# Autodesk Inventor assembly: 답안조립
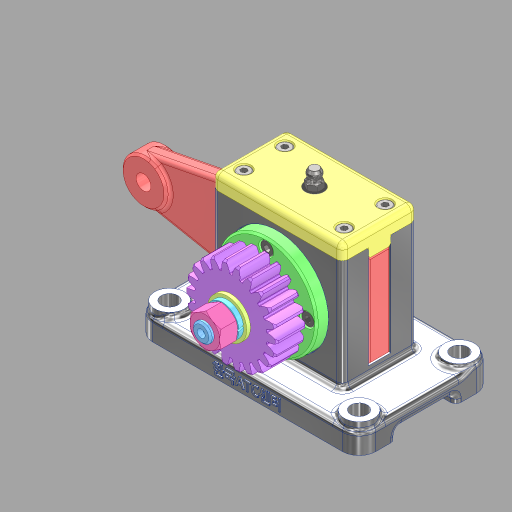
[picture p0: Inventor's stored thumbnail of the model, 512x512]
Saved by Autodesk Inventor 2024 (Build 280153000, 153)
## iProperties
Created: 2025-04
Part Number: 답안조립
Document SubType Name: Assembly
Designer: kh_501
Author: kh_501
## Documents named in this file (15)
- C:\Users\kh_501\Desktop\750404V1011\답안조립.iam
- C:\Users\kh_501\Desktop\750404V1011\본체.ipt
- C:\Users\kh_501\Desktop\750404V1011\그리스 니플 M6x0.75\그리스 니플 M6x0.75.ipt
- C:\Users\kh_501\Desktop\750404V1011\로드\로드.ipt
- C:\Users\kh_501\Desktop\750404V1011\스퍼기어\스퍼기어.ipt
- C:\Users\kh_501\Desktop\750404V1011\스프링와셔 M10\스프링와셔 M10.ipt
- C:\Users\kh_501\Desktop\750404V1011\실링\실링.ipt
- C:\Users\kh_501\Desktop\750404V1011\앞커버\앞커버.ipt
- C:\Users\kh_501\Desktop\750404V1011\윗커버\윗커버.ipt
- C:\Users\kh_501\Desktop\750404V1011\육각 너트 M10\육각 너트 M10.ipt
- C:\Users\kh_501\Desktop\750404V1011\육각 소켓 머리 볼트 M4x10\육각 소켓 머리 볼트 M4x10.ipt
- C:\Users\kh_501\Desktop\750404V1011\편심축\편심축.ipt
- C:\Users\kh_501\Desktop\750404V1011\평와셔 M10\평와셔 M10.ipt
- C:\Users\kh_501\Desktop\750404V1011\평행키 4x4x10\평행키 4x4x10.ipt
- C:\Users\kh_501\Desktop\750404V1011\플랜지 오일레스 부시\플랜지 오일레스 부시.ipt
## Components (3 placed, 2 different names)
1. 그리스 니플 M6x0.75:1 — 각도:9
2. 플랜지 오일레스 부시:1 — 각도:14
3. 플랜지 오일레스 부시:2 — 각도:15
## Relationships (3: Angle 3)
- 각도:9 [Angle]: 그리스 니플 M6x0.75:1
- 각도:14 [Angle]: 플랜지 오일레스 부시:1
- 각도:15 [Angle]: 플랜지 오일레스 부시:2
